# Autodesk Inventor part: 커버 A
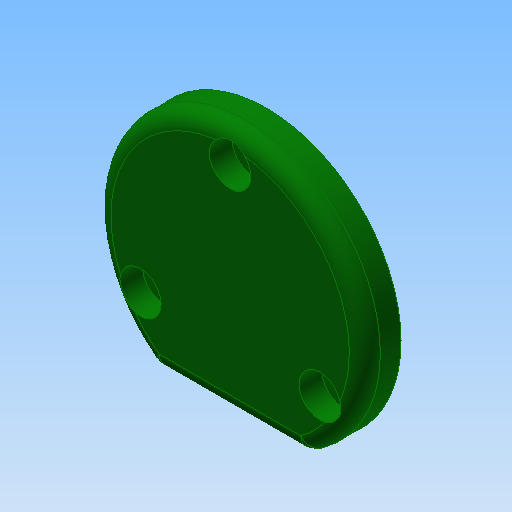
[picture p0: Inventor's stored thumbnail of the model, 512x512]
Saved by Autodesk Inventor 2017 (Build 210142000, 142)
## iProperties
Created: 2020-04
Part Number: 커버 A
Material: 알루미늄 6061
Document SubType Name: Modeling
Designer: mduedu
Density: 2.71 g/cm^3
Mass: 30.8954 g
Surface Area: 61.0157 cm^2
Volume: 11.4005 cm^3
Appearance: 진녹색
Author: mduedu
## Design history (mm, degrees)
sketch "스케치1"
  geometry: C1 r 26 at (0, 0); 1 further point
  constraints: 1 centre point, 1 coincident
  dimensions: "d0" = 52 diameter of C1
extrude "돌출1" new body sketch "스케치1" distance "d1" = 7; taper "d2" = 0 deg
sketch "스케치2"
  geometry: L1 (-14.62, -21.5)-(14.62, -21.5); A1 r 26 centre (0, 0) between (-14.62, -21.5) and (14.62, -21.5) reference; 1 further point
  constraints: 2 end point, 2 point on circle, 1 horizontal
  dimensions: "d3" = 21.5 distance from line of L1 point (0, 0)
extrude "돌출2" cut sketch "스케치2" stored distance "d4" = 7; taper "d5" = 0 deg
fillet "모깎기1" dims "d6" = 3
fillet "모깎기2" dims "d7" = 3
sketch "스케치3" dims "d8" = 40
  geometry: 3 further points
  constraints: 2 vertical alignment, 1 coincident, 2 other
hole "구멍1" sketch "스케치3" at (0, 20) diameter "d9" = 4.5; stored, may be unused: countersink angle "d13" = 90 deg, drill point angle "d15" = 118 deg; dims "d10" = 6, "d11" = 8, "d12" = 4.4, "d14" = 8
sketch "스케치4"
  geometry: C1 r 16 at (0, 0); 1 further point
  constraints: 1 centre point, 1 coincident
  dimensions: "d19" = 32 diameter of C1
extrude "돌출3" join sketch "스케치4" distance "d20" = 3; taper "d21" = 0 deg
sketch "스케치5"
  geometry: C1 r 14 at (0, 0); 1 further point
  constraints: 1 centre point, 1 coincident
  dimensions: "d22" = 28 diameter of C1
extrude "돌출4" cut sketch "스케치5" distance "d23" = 7; taper "d24" = 0 deg
fillet "모깎기3" dims "d25" = 3
chamfer "모따기1" distance "d26" = 0.5; stored, may be unused: second distance "d27" = 2, angle "d28" = 45 deg
node "솔리드1"
pattern_circular "원형 패턴1" dims angle "d17" = 360 deg
node "투영된 루프1"
